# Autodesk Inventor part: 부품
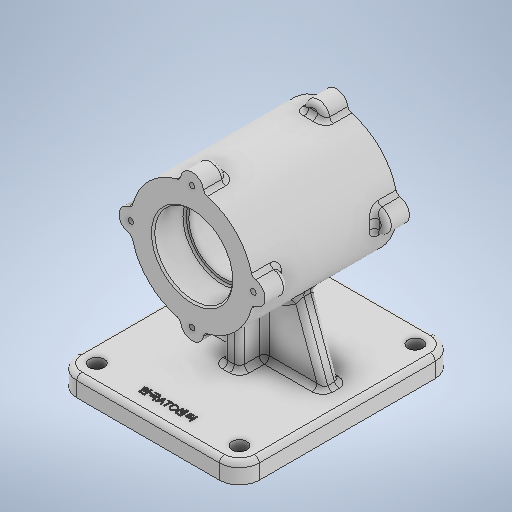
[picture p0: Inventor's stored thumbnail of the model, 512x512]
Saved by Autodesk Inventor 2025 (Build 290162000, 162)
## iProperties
Created: 2024-08
Part Number: 부품
Material: 일반
Document SubType Name: Modeling
Designer: hsj03
Density: 1 g/cm^3
Appearance: 기본값
Mass: 450.138 g
Surface Area: 796.667 cm^2
Volume: 450.138 cm^3
Author: hsj03
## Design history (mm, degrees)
sketch "스케치1"
  geometry: C1 r 37 at (0, 0); 1 further point
  constraints: 1 centre point, 1 coincident
  dimensions: "d1" = 37 radius of C1
extrude "돌출1" new body sketch "스케치1" stored distance "d2" = 87; taper "d3" = 0 deg
node "작업 평면1"
sketch "스케치2"
  geometry: L1 (55, 70)-(55, -60); L2 (55, -60)-(-55, -60); L3 (-55, -60)-(-55, 70); L4 (-55, 70)-(55, 70); L5 (-37, -43.5)-(37, -43.5) reference; L6 (37, 43.5)-(-37, 43.5) reference; L7 (0, 70)-(0, -60); L8 (55, 0)-(-55, 0); 2 further points
  constraints: 12 end point, 3 midpoint, 2 coincident, 2 parallel, 2 point on line, 2 vertical, 1 horizontal, 1 perpendicular
  dimensions: "d6" = 70 distance of L1.start L8.start; "d7" = 130 distance between parallel lines of L4 L2; "d8" = 110 distance of L1.end L2.end
extrude "돌출2" join sketch "스케치2" distance "d9" = 12; taper "d10" = 0 deg
sketch "스케치3"
  geometry: L1 (-5, -20)-(-5, 20); L2 (-5, 20)-(5, 20); L3 (5, 20)-(5, -20); L4 (5, -20)-(-5, -20); L5 (-5, -20)-(5, 20); L6 (-5, 20)-(5, -20); L7 (-55, -70)-(55, -70) reference; 3 further points
  constraints: 12 end point, 3 midpoint, 2 parallel, 1 coincident, 1 perpendicular, 1 vertical
  dimensions: "d11" = 70 distance from line of L7 point (0, 0); "d12" = 10 distance of L1.end L2.end; "d13" = 40 distance of L1.start L1.end
extrude "돌출3" join sketch "스케치3" taper "d10" = 0 deg; stored distance "d14" = 12; taper "d15" = 0 deg
node "작업 평면2"
sketch "스케치4"
  geometry: L1 (-25.336, -26.964)-(25.336, -26.964); L2 (25.336, -26.964)-(41, -70); L3 (41, -70)-(-41, -70); L4 (-41, -70)-(-25.336, -26.964); L5 (55, -70)-(-55, -70) reference; L6 (0, 0)-(0, -82); L7 (-77, -82)-(77, -82) reference; L8 (-55, -82)-(-55, -70) reference; A1 r 37 centre (0, 0) between (-25.336, -26.964) and (25.336, -26.964) reference
  constraints: 10 end point, 2 horizontal, 2 point on circle, 1 coincident, 1 midpoint, 1 point on line, 1 vertical
  dimensions: "d16" = 110 deg angle of L5 L2; "d17" = 110 deg angle of L5 L4; "d18" = 14 distance of L5.start L2.end; "d89" = 14 distance from line of L8 L3.end (derived)
extrude "돌출4" join sketch "스케치4" stored distance "d19" = 10; taper "d20" = 0 deg
sketch "스케치5"
  geometry: C1 r 37 at (0, 0) reference; C2 r 7 at (0, 37); 1 further point
  constraints: 2 vertical alignment, 1 centre point, 1 other
  dimensions: "d22" = 7 radius of C2
extrude "돌출5" join sketch "스케치5" distance "d23" = 14; taper "d24" = 0 deg
fillet "모깎기1" dims "d28" = 12
sketch "스케치6"
  geometry: A1 r 37 centre (0, 0) between (36.338, 6.969) and (6.969, 36.338) reference; 1 further point
  constraints: 1 coincident
hole "구멍1" sketch "스케치6" at (0, 0) diameter "d29" = 42; stored, may be unused: countersink angle "d33" = 90 deg, drill point angle "d35" = 118 deg; dims "d30" = 6, "d31" = 47, "d32" = 19, "d34" = 8
sketch "스케치7"
  geometry: A1 r 37 centre (0, 0) between (36.338, 6.969) and (6.969, 36.338) reference; 1 further point
  constraints: 1 coincident
hole "구멍2" sketch "스케치7" at (0, 0) diameter "d36" = 42; stored, may be unused: countersink angle "d40" = 90 deg, drill point angle "d42" = 118 deg; dims "d37" = 6, "d38" = 47, "d39" = 19, "d41" = 8
fillet "모깎기2" dims "d43" = 1
chamfer "모따기1" distance "d44" = 1; stored, may be unused: second distance "d45" = 2, angle "d46" = 45 deg
sketch "스케치8"
  geometry: A1 r 7 centre (-37, 0) between (-36.338, 6.969) and (-36.338, -6.969) reference; A2 r 7 centre (0, 37) between (6.969, 36.338) and (-6.969, 36.338) reference; A3 r 7 centre (0, -37) between (-6.969, -36.338) and (6.969, -36.338) reference; A4 r 7 centre (37, 0) between (36.338, -6.969) and (36.338, 6.969) reference; 5 further points
  constraints: 4 coincident
hole "구멍3" sketch "스케치8" at (-37, 0), (0, 37), (0, -37), (37, 0) diameter "d47" = 3.242; stored, may be unused: countersink angle "d51" = 90 deg, drill point angle "d53" = 120 deg; dims "d48" = 8, "d49" = 47, "d50" = 19, "d52" = 10
sketch "스케치9"
  geometry: A1 r 7 centre (0, 37) between (6.969, 36.338) and (-6.969, 36.338) reference; A2 r 7 centre (-37, 0) between (-36.338, 6.969) and (-36.338, -6.969) reference; A3 r 7 centre (0, -37) between (-6.969, -36.338) and (6.969, -36.338) reference; A4 r 7 centre (37, 0) between (36.338, -6.969) and (36.338, 6.969) reference; 4 further points
  constraints: 4 coincident
hole "구멍4" sketch "스케치9" at (0, 37), (-37, 0), (0, -37), (37, 0) diameter "d54" = 3.242; stored, may be unused: countersink angle "d58" = 90 deg, drill point angle "d60" = 120 deg; dims "d55" = 8, "d56" = 4, "d57" = 2, "d59" = 10
sketch "스케치10"
  geometry: L1 (0, -70)-(0, 60); L2 (-43, -70)-(43, -70) reference; L3 (43, 60)-(-43, 60) reference; L4 (-55, -5)-(55, -5); L5 (-55, 48)-(-55, -58) reference; L6 (55, -58)-(55, 48) reference; 4 further points
  constraints: 4 end point, 4 midpoint, 2 symmetric about line, 1 horizontal, 1 vertical
  dimensions: "d68" = 86 distance of point (43, -58) point (-43, -58); "d69" = 106 distance of point (-43, -58) point (-43, 48); "d70" = 12 distance from line of L3 point (-43, 48); "d87" = 12 distance from line of L5 point (-43, 48)
hole "구멍5" sketch "스케치10" at (-43, 48), (43, 48), (43, -58), (-43, -58) diameter "d61" = 9; stored, may be unused: countersink angle "d65" = 90 deg, drill point angle "d67" = 0 deg; dims "d62" = 8, "d63" = 4, "d64" = 2, "d66" = 10
fillet "모깎기3" dims "d71" = 3
fillet "모깎기4" dims "d72" = 3
fillet "모깎기5" dims "d73" = 3
fillet "모깎기6" dims "d80" = 3
sketch "스케치13"
  geometry: L1 (-43, -70)-(43, -70) reference; 3 further points
  constraints: 1 midpoint, 1 vertical alignment, 1 other
  dimensions: "d83" = 12 distance of point (0, -70) point (0, -58); "d84" = 58 distance of point (0, 0) point (0, -58) (derived)
feature "엠보싱1" sketch "스케치13" dims "d85" = 0.5, "d86" = 0
fillet "모깎기7" dims "d88" = 3
feature "͞耀͠耀͢耀ͤ耀ͦ耀ͨ耀ͪ耀ͬ耀" dims "d1" = 37, "d2" = 87, "d3" = 0, "d4" = -82, "d6" = 70, "d7" = 130, "d8" = 110, "d9" = 12, "d10" = 0, "d11" = 70, "d12" = 10, "d13" = 40, "d14" = 12, "d15" = 0, "d16" = 110 deg, "d17" = 110 deg, "d18" = 14, "d19" = 10, "d20" = 0, "d22" = 7, "d23" = 14, "d24" = 0, "d25" = 40, "d26" = 360 deg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
node "솔리드1"
pattern_circular "원형 패턴1" dims angle "d26" = 360 deg
mirror "미러1"
node "투영된 루프1"
feature "A9D066F2-1C7D-4E18-AEED-F7BC21143FA4" dims "d29" = 42, "d30" = 6, "d31" = 47, "d32" = 19, "d33" = 90 deg, "d34" = 8, "d35" = 118 deg
